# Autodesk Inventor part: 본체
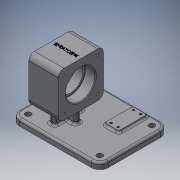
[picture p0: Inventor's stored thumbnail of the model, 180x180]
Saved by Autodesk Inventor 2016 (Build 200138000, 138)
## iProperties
Created: 2019-09
Part Number: 본체
Material: 알루미늄 6061
Document SubType Name: Modeling
Designer: mduedu
Density: 2.71 g/cm^3
Mass: 636.366 g
Surface Area: 520.125 cm^2
Volume: 234.821 cm^3
Appearance: 기본값
Author: mduedu
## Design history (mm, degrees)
sketch "스케치1"
  geometry: L1 (42, -62)-(-84, -62); L2 (-84, -62)-(-84, 36); L3 (-84, 36)-(42, 36); L4 (42, 36)-(42, -62); 1 further point
  constraints: 8 end point, 2 parallel, 1 horizontal, 1 perpendicular
  dimensions: "d0" = 36 distance from line of L3 point (0, 0); "d1" = 98 distance of L1.end L2.end; "d2" = 42 distance from line of L4 point (0, 0); "d3" = 126 distance of L2.end L3.end
extrude "돌출1" new body sketch "스케치1" distance "d4" = 9; taper "d5" = 0 deg
sketch "스케치2"
  geometry: L1 (0, -62)-(0, 36) reference; L2 (27, -32)-(91, -32); L3 (91, -32)-(91, 32); L4 (91, 32)-(27, 32); L5 (27, 32)-(27, -32); L6 (27, -32)-(91, 32); L7 (91, -32)-(27, 32); 3 further points
  constraints: 12 end point, 3 midpoint, 2 parallel, 1 horizontal, 1 horizontal alignment, 1 perpendicular
  dimensions: "d87" = 64 distance of L4.end L3.end; "d88" = 64 distance of L3.end L2.end; "d89" = 59 distance from line of point (59, 0) L1
extrude "돌출2" join sketch "스케치2" stored distance "d8" = 42; taper "d9" = 0 deg
sketch "스케치3"
  geometry: L1 (-17, 4)-(17, 4); L2 (17, 4)-(17, -4); L3 (17, -4)-(-17, -4); L4 (-17, -4)-(-17, 4); L5 (-4, 20)-(4, 20); L6 (4, 20)-(4, -20); L7 (4, -20)-(-4, -20); L8 (-4, -20)-(-4, 20); 5 further points
  constraints: 16 end point, 4 midpoint, 4 parallel, 2 horizontal, 2 horizontal alignment, 2 perpendicular, 2 vertical alignment
  dimensions: "d10" = 8 distance of L5.start L5.end; "d12" = 8 distance of L1.end L2.end; "d13" = 34 distance of L2.end L3.end; "d14" = 40 distance of L5.end L6.end
extrude "돌출3" join sketch "스케치3" stored distance "d15" = 42; taper "d16" = 0 deg
sketch "스케치4"
  geometry: L1 (-32, 91)-(-32, 27) reference; L2 (32, 91)-(-32, 91) reference; L3 (32, 27)-(32, 91) reference; L4 (-32, 27)-(32, 27) reference; C1 r 21 at (0, 59); 3 further points
  constraints: 2 midpoint, 1 centre point, 1 horizontal alignment, 1 vertical alignment
  dimensions: "d17" = 42 diameter of C1
extrude "돌출4" cut sketch "스케치4" distance "d18" = 15; taper "d19" = 0 deg
hole "구멍1" diameter "d22" = 36; stored, may be unused: countersink angle "d26" = 90 deg, drill point angle "d28" = 118 deg; dims "d20" = 10, "d21" = 10, "d23" = 6, "d24" = 4, "d25" = 2, "d27" = 8
fillet "모깎기1" dims "d29" = 0.3
chamfer "모따기1" distance "d30" = 1; stored, may be unused: second distance "d31" = 2, angle "d32" = 45 deg
fillet "모깎기9" dims "d90" = 8
sketch "스케치11"
  geometry: L1 (-24, 27)-(24, 27) reference; L2 (32, 35)-(32, 83) reference; L3 (24, 91)-(-24, 91) reference; L4 (-32, 83)-(-32, 35) reference; C1 r 22 at (0, 59) reference; A1 r 8 centre (-24, 35) between (-32, 35) and (-24, 27) reference; A2 r 8 centre (24, 35) between (24, 27) and (32, 35) reference; A3 r 8 centre (24, 83) between (32, 83) and (24, 91) reference; A4 r 8 centre (-24, 83) between (-24, 91) and (-32, 83) reference; 5 further points
  constraints: 4 coincident
hole "구멍6" sketch "스케치11" at (-24, 83), (24, 83), (24, 35), (-24, 35) diameter "d91" = 3.242; stored, may be unused: countersink angle "d95" = 90 deg, drill point angle "d97" = 118 deg; dims "d92" = 8, "d93" = 4, "d94" = 2, "d96" = 10
fillet "모깎기2" dims "d44" = 12
sketch "스케치6"
  geometry: L1 (-42, 50)-(-42, -24) reference; L2 (-30, -36)-(72, -36) reference; L3 (84, -24)-(84, 50) reference; L4 (72, 62)-(-30, 62) reference; L5 (17, 4)-(17, -4) reference; L6 (17, -4)-(4, -4) reference; L7 (4, -4)-(4, -20) reference; L8 (4, -20)-(-4, -20) reference; L9 (-4, -20)-(-4, -4) reference; L10 (-4, -4)-(-17, -4) reference; L11 (-17, -4)-(-17, 4) reference; L12 (-17, 4)-(-4, 4) reference; L13 (-4, 4)-(-4, 20) reference; L14 (-4, 20)-(4, 20) reference; L15 (4, 20)-(4, 4) reference; L16 (4, 4)-(17, 4) reference; A1 r 12 centre (-30, 50) between (-30, 62) and (-42, 50) reference; A2 r 12 centre (-30, -24) between (-42, -24) and (-30, -36) reference; A3 r 12 centre (72, -24) between (72, -36) and (84, -24) reference; A4 r 12 centre (72, 50) between (84, 50) and (72, 62) reference; 5 further points
  constraints: 4 coincident
hole "구멍3" sketch "스케치6" at (-30, 50), (72, 50), (72, -24), (-30, -24) diameter "d45" = 8; stored, may be unused: countersink angle "d49" = 90 deg, drill point angle "d51" = 118 deg; dims "d46" = 8, "d47" = 4, "d48" = 2, "d50" = 10
sketch "스케치7"
  geometry: L1 (38, 57)-(58, 57); L2 (58, 57)-(58, 17); L3 (58, 17)-(38, 17); L4 (38, 17)-(38, 57); L5 (72, 62)-(-30, 62) reference; 3 further points
  constraints: 8 end point, 2 midpoint, 2 parallel, 1 horizontal, 1 perpendicular
  dimensions: "d52" = 48 horizontal distance of point (48, 57) point (0, 0); "d53" = 20 distance of L1.start L1.end; "d54" = 40 distance of L1.end L2.end; "d55" = 25 distance from line of point (38, 37) L5
extrude "돌출5" join sketch "스케치7" distance "d56" = 3; taper "d57" = 0 deg
fillet "모깎기3" dims "d58" = 3
fillet "모깎기4" dims "d59" = 3
fillet "모깎기5" dims "d60" = 3
fillet "모깎기6" dims "d61" = 3
fillet "모깎기7" dims "d62" = 3
fillet "모깎기8" dims "d63" = 3
sketch "스케치8"
  geometry: L1 (72, 62)-(58.317, 62) reference; L2 (84, -24)-(84, 50) reference; C1 r 1.5 at (43, 53); C2 r 1.5 at (53, 21); 1 further point
  constraints: 2 centre point, 1 equal radius
  dimensions: "d64" = 3 diameter of C1; "d65" = 9 distance from line of C1.centre L1; "d66" = 32 vertical distance of C2.centre C1.centre; "d67" = 10 horizontal distance of C2.centre C1.centre; "d68" = 31 distance from line of L2 C2.centre
hole "구멍4" sketch "스케치8" at (43, 53), (53, 21) diameter "d69" = 3; stored, may be unused: countersink angle "d73" = 90 deg, drill point angle "d75" = 118 deg; dims "d70" = 8, "d71" = 4, "d72" = 2, "d74" = 6
sketch "스케치9"
  geometry: C1 r 1.5 at (43, 53) reference; C2 r 1.5 at (53, 21) reference; 3 further points
  constraints: 2 horizontal alignment, 2 vertical alignment
hole "구멍5" sketch "스케치9" at (53, 53), (43, 21) diameter "d76" = 3.242; stored, may be unused: countersink angle "d80" = 90 deg, drill point angle "d82" = 118 deg; dims "d77" = 6, "d78" = 4, "d79" = 2, "d81" = 8
sketch "스케치10"
  geometry: 2 further points
  constraints: 1 coincident, 1 other
feature "엠보싱1" sketch "스케치10" dims "d0" = 36, "d1" = 98, "d2" = 42, "d3" = 126, "d12" = 8, "d13" = 34, "d85" = 0.5, "d86" = 0
node "솔리드1"
mirror "대칭1"
mirror "대칭2"
node "투영된 루프1"
node "투영된 루프2"
